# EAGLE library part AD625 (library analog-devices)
Programmable Gain Instrumentation Amplifier Source: http://www.analog.com/static/imported-files/data_sheets/AD625.pdf
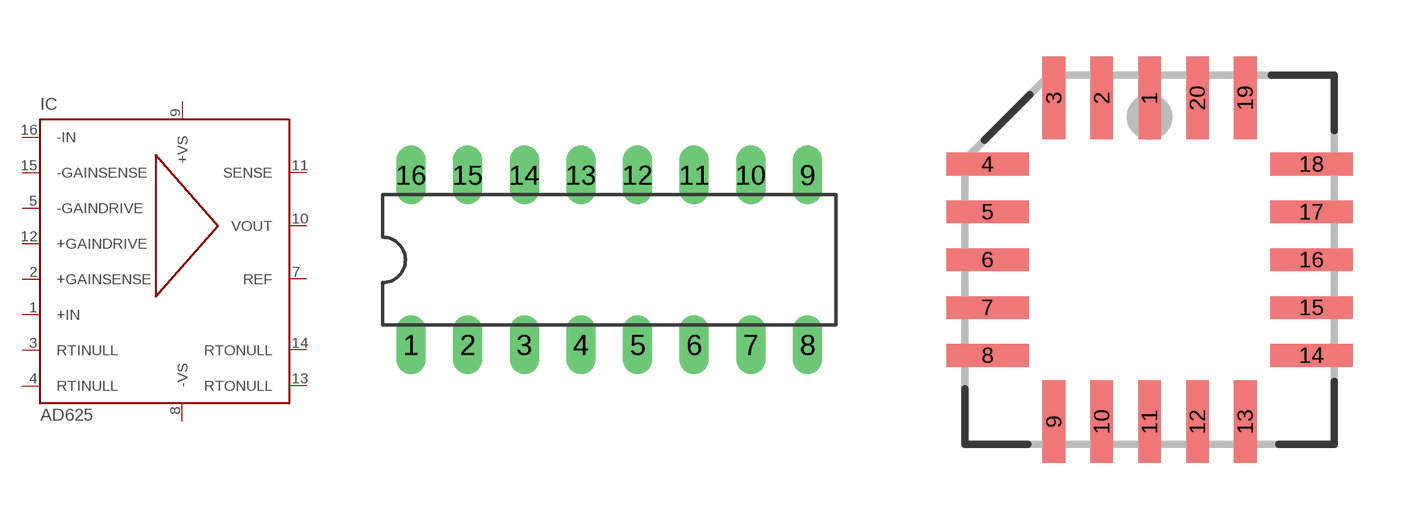
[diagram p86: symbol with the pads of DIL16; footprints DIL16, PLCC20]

Designator prefix IC

## AD625N (MPN: AD625KNZ; OC_FARNELL: 1438353; OC_NEWARK: 15P0739)  [DIL16]
1  +IN  in
2  +GAINSENSE  in
3  RTINULL  pas
4  RTINULL  pas
5  -GAINDRIVE  in
7  REF  in
8  -VS  in
9  +VS  in
10  VOUT  out
11  SENSE  in
12  +GAINDRIVE  in
13  RTONULL  pas
14  RTONULL  pas
15  -GAINSENSE  in
16  -IN  in

## AD625D (MPN: AD625KNZ; OC_FARNELL: 3182289; OC_NEWARK: 15P0739)  [DIL16]
Pads as for DIL16

## AD625E (OC_FARNELL: unknown; OC_NEWARK: unknown)  [PLCC20]
2  +IN  in
3  +GAINSENSE  in
4  RTINULL  pas
5  RTINULL  pas
7  +GAINDRIVE  in
9  REF  in
10  -VS  in
12  +VS  in
13  VOUT  out
14  SENSE  in
15  -GAINDRIVE  in
17  RTONULL  pas
18  RTONULL  pas
19  -GAINSENSE  in
20  -IN  in

## Footprint DIL16 (pad centres in mm)
Dual In Line Package
drill 0.813 long: 1 -8.89,-3.81; 2 -6.35,-3.81; 3 -3.81,-3.81; 4 -1.27,-3.81; 5 1.27,-3.81; 6 3.81,-3.81; 7 6.35,-3.81; 8 8.89,-3.81; 9 8.89,3.81; 10 6.35,3.81; 11 3.81,3.81; 12 1.27,3.81; 13 -1.27,3.81; 14 -3.81,3.81; 15 -6.35,3.81; 16 -8.89,3.81

## Footprint PLCC20 (pad centres in mm)
Plastic Leaded Chip Carrier IPC standard
smd 0.6 x 2.2: 1 0,4.3; 2 -1.27,4.3; 3 -2.54,4.3; 9 -2.54,-4.3; 10 -1.27,-4.3; 11 0,-4.3; 12 1.27,-4.3; 13 2.54,-4.3; 19 2.54,4.3; 20 1.27,4.3
smd 2.2 x 0.6: 4 -4.3,2.54; 5 -4.3,1.27; 6 -4.3,0; 7 -4.3,-1.27; 8 -4.3,-2.54; 14 4.3,-2.54; 15 4.3,-1.27; 16 4.3,0; 17 4.3,1.27; 18 4.3,2.54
